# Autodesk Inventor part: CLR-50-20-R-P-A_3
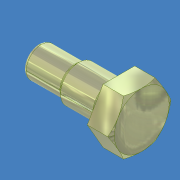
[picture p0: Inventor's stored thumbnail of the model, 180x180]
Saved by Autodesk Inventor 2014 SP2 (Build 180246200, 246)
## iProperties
Shininess: 64.0
Length Units: 11269
Angle Units: 11279
Time Units: 11290
Mass Units: 11283
Length Display Precision: 3
Angle Display Precision: 2
Compacted: True
Part Number: CLR-50-20-R-P-A_3
Document SubType Name: Modeling
Created: 2004-03
Material: Allgemein
Cost Center: 0 kg
Designer: Peter Kastler
Manufacturer: Standard
Standards Organization: Custom
Density: 1 g/cm^3
Appearance: Metall - Zinkchromat
Density: 0.0
Volumn: 0.0
Area: 0.0
PropertySet Name: Model Information
Control State: 0
Master: False
Checked Out: False
Übersetzungsnorm: STEP AP203
Dateiname: 535459_CLR_50_20_R_P_A.stp
Postprozessor: Build: 081d, Release: 8 SP1 - Date: Tue 01/26/2004
Gesendete Einheiten: MILLIMETERS
Unbestimmtheit: 1e-06
TotalMass: 0 kg
Cideon_Mass: 0.0
Cideon_Mass_Unit: kg
Cideon_Area: 0,002 m^2
Cideon_User: konstruktion
Cideon_SaveDate: 10.10.2018
Cideon_SaveTime: 09:12:01
Author: Peter Kastler
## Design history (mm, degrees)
feature "Basis1"
node "Volumenkörper1"
node "Volumenkörper"
node "Flächenkörper"
